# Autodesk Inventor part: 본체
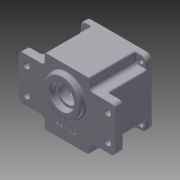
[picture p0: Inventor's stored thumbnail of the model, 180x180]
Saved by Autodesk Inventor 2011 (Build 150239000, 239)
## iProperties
Created: 2014-12
Part Number: 본체
Material: 알루미늄-6061
Document SubType Name: Modeling
Designer: Administrator
Mass: 705.365 g
Surface Area: 672.962 cm^2
Volume: 260.282 cm^3
Density: 2.71 g/cm^3
Author: Administrator
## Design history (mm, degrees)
sketch "스케치1"
  geometry: L1 (-45, -45)-(45, -45); L2 (45, -45)-(45, 45); L3 (45, 45)-(-45, 45); L4 (-45, 45)-(-45, -45); 3 further points
  constraints: 8 end point, 2 midpoint, 2 parallel, 1 horizontal, 1 horizontal alignment, 1 perpendicular, 1 vertical alignment
  dimensions: "d0" = 90 distance of L3.end L2.end; "d1" = 90 distance of L2.end L1.end
extrude "돌출1" new body sketch "스케치1" distance "d2" = 70; taper "d3" = 0 deg
sketch "스케치2"
  geometry: L1 (-65, 30)-(65, 30); L2 (65, 30)-(65, -30); L3 (65, -30)-(-65, -30); L4 (-65, -30)-(-65, 30); 3 further points
  constraints: 8 end point, 2 midpoint, 2 parallel, 1 horizontal, 1 horizontal alignment, 1 perpendicular, 1 vertical alignment
  dimensions: "d4" = 130 distance of L1.start L1.end; "d5" = 60 distance of L3.end L1.start
extrude "돌출2" join sketch "스케치2" distance "d6" = 12; taper "d7" = 0 deg
sketch "스케치3"
  geometry: C1 r 40 at (0, 0); 1 further point
  constraints: 1 centre point, 1 coincident
  dimensions: "d8" = 80 diameter of C1
extrude "돌출3" cut sketch "스케치3" distance "d9" = 9; taper "d10" = 0 deg
sketch "스케치4"
  geometry: C1 r 40 at (0, 0) reference; C2 r 39 at (0, 0)
  constraints: 1 centre point, 1 coincident
  dimensions: "d11" = 78 diameter of C2
extrude "돌출4" cut sketch "스케치4" distance "d12" = 52; taper "d13" = 0 deg
sketch "스케치5"
  geometry: C1 r 39 at (0, 0) reference; A1 r 20.5 centre (0, 11) between (11.115, -6.225) and (-11.115, -6.225); A2 r 14 centre (0, -20) between (-10.493, -10.732) and (10.493, -10.732); A3 r 3 centre (12.742, -8.746) between (11.115, -6.225) and (10.493, -10.732); A4 r 3 centre (-12.742, -8.746) between (-10.493, -10.732) and (-11.115, -6.225)
  constraints: 8 point on circle, 4 centre point, 4 tangent, 2 vertical alignment
  dimensions: "d14" = 41 diameter of A1; "d15" = 28 diameter of A2; "d16" = 11 distance of A1.centre C1.centre; "d17" = 20 distance of A2.centre C1.centre; "d18" = 6 diameter of A3; "d19" = 6 diameter of A4
extrude "돌출5" join sketch "스케치5" distance "d20" = 7; taper "d21" = 0 deg
sketch "스케치6"
  geometry: C1 r 25 at (0, 11); 1 further point
  constraints: 1 centre point, 1 vertical alignment
  dimensions: "d22" = 50 diameter of C1; "d23" = 11 distance of C1.centre point (0, 0)
extrude "돌출6" join sketch "스케치6" distance "d24" = 7; taper "d25" = 0 deg
sketch "스케치7"
  geometry: L1 (45, 30)-(45, 45) reference; L2 (45, 45)-(-45, 45) reference; L3 (45, 30)-(30, 30); L4 (30, 30)-(30, 45); L5 (30, 45)-(45, 45); L6 (45, 45)-(45, 30); 1 further point
  constraints: 8 end point, 2 parallel, 1 horizontal, 1 perpendicular, 1 point on line
  dimensions: "d26" = 30 distance from line of L4 point (0, 0)
extrude "돌출7" cut sketch "스케치7" distance "d27" = 63; taper "d28" = 0 deg
sketch "스케치8"
  geometry: C1 r 17.5 at (0, 11); A1 r 20.5 centre (0, 11) between (11.115, -6.225) and (-11.115, -6.225) reference; 1 further point
  constraints: 1 centre point, 1 coincident
  dimensions: "d32" = 35 diameter of C1
extrude "돌출8" cut sketch "스케치8" distance "d33" = 10; taper "d34" = 0 deg
sketch "스케치9"
  geometry: C1 r 17.5 at (0, 0) reference; C2 r 12.5 at (0, 0); 1 further point
  constraints: 1 centre point, 1 coincident
  dimensions: "d35" = 25 diameter of C2
extrude "돌출9" cut sketch "스케치9" distance "d36" = 5; taper "d37" = 0 deg
sketch "스케치10"
  geometry: C1 r 11 at (0, -20); A1 r 14 centre (0, -20) between (-10.493, -10.732) and (10.493, -10.732) reference; 1 further point
  constraints: 1 centre point, 1 coincident
  dimensions: "d38" = 22 diameter of C1
extrude "돌출10" cut sketch "스케치10" distance "d39" = 7; taper "d40" = 0 deg
sketch "스케치11"
  geometry: C1 r 11 at (0, 0) reference; C2 r 9.5 at (0, 0); 1 further point
  constraints: 1 centre point, 1 coincident
  dimensions: "d41" = 19 diameter of C2
extrude "돌출11" cut sketch "스케치11" distance "d42" = 1; taper "d43" = 0 deg
sketch "스케치12"
  geometry: C1 r 25 at (0, 0) reference; C2 r 16 at (0, 0); 1 further point
  constraints: 1 centre point, 1 coincident
  dimensions: "d44" = 32 diameter of C2
extrude "돌출12" cut sketch "스케치12" distance "d45" = 8; taper "d46" = 0 deg
sketch "스케치13"
  geometry: L1 (0, 0)-(24.749, 24.749); L2 (0, 0)-(35, 0); C1 r 39 at (0, 0) reference; A1 r 35 centre (0, 0) between (24.749, 24.749) and (27.412, 21.762); A2 r 4 centre (24.749, 24.749) between (21.809, 27.462) and (27.462, 21.809); A3 r 39 centre (0, 0) between (32.777, 21.134) and (21.134, 32.777); A4 r 3.5 centre (29.836, 19.238) between (32.777, 21.134) and (27.412, 21.762); A5 r 3.5 centre (19.238, 29.836) between (21.762, 27.412) and (21.134, 32.777)
  constraints: 13 point on circle, 5 centre point, 4 end point, 4 tangent, 3 coincident, 1 equal length, 1 horizontal
  dimensions: "d47" = 70 diameter of A1; "d48" = 45 deg angle of L2 L1; "d49" = 8 diameter of A2; "d50" = 7 diameter of A4; "d51" = 7 diameter of A5
extrude "돌출13" join sketch "스케치13" stored distance "d52" = 8; taper "d53" = 0 deg
fillet "모깎기1" dims "d57" = 8
hole "Hole1" diameter "d60" = 7; stored, may be unused: countersink angle "d64" = 90 deg, drill point angle "d66" = 0 deg; dims "d58" = 10, "d59" = 10, "d61" = 6, "d62" = 4, "d63" = 2, "d65" = 8
sketch "스케치14"
  geometry: 2 further points
  dimensions: "d70" = 17.5 vertical distance of point (-55, 17.5) point (0, 0); "d71" = 55 horizontal distance of point (0, 0) point (-55, 17.5)
hole "Hole2" sketch "스케치14" at (-55, 17.5) diameter "d72" = 9; stored, may be unused: countersink angle "d76" = 90 deg, drill point angle "d78" = 0 deg; dims "d73" = 6, "d74" = 4, "d75" = 2, "d77" = 8
hole "Hole3" diameter "d87" = 3.459; stored, may be unused: countersink angle "d91" = 90 deg, drill point angle "d93" = 118 deg; dims "d85" = 10, "d86" = 10, "d88" = 12, "d89" = 4, "d90" = 2, "d92" = 15
fillet "모깎기2" dims "d97" = 5
fillet "모깎기3" dims "d98" = 2, "d99" = 0.3
chamfer "모따기1" distance "d100" = 1; stored, may be unused: second distance "d101" = 2, angle "d102" = 45 deg
sketch "스케치15"
  geometry: L1 (-28, -45)-(28, -45) reference; 2 further points
  constraints: 1 vertical alignment, 1 other
  dimensions: "d103" = 15 distance from line of L1 point (0, -30)
feature "엠보싱1" sketch "스케치15" dims "d0" = 90, "d1" = 90, "d104" = 0.5, "d105" = 0
node "솔리드1"
pattern_circular "원형 패턴1" dims angle "d30" = 360 deg
pattern_circular "원형 패턴2" dims angle "d55" = 360 deg
pattern_circular "원형 패턴3" dims angle "d68" = 360 deg
pattern_linear "직사각형 패턴1" dims "d81" = 110, "d84" = 35
pattern_circular "원형 패턴4" dims angle "d95" = 360 deg
